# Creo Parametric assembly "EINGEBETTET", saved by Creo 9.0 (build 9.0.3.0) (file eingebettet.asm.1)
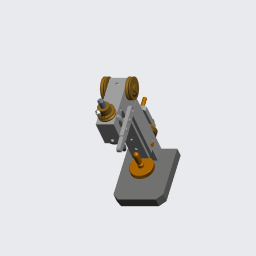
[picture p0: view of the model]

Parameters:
  DATUM = "XX.XX.XX"
  ERSTELLER = "ARINDA"
  TEILETYP = "Montage-Baugruppe"

Other parameters: MASSE

Created from: ARINDA-STARTBAUGRUPPE.ASM

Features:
  1. coordinate system "ACS0"
  2. datum plane "ADTM1", "A_RECHTS_Y-Z"
  3. datum plane "ADTM2", "A_OBEN_X-Z"
  4. datum plane "ADTM3", "A_VORNE_X-Y"
  5. datum axis "AA_1"
  6. datum axis "AA_2"
  7. datum axis "AA_3"
  8. coordinate system "BOHRMASCHINE_ASM"
  9. imported feature "Import-ke ID 40"
  10. component

Other named items: A_BASIS, A_X-ACHSE, A_Y-ACHSE, A_Z-ACHSE, NOTE_0

Notes: NOT SPECIFIED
